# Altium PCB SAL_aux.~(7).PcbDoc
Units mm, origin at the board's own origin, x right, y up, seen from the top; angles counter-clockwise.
Board outline 56 x 58 mm, 2 copper layers (Top Layer, Bottom Layer); 28 components, 47 nets, 135 pads, 5 vias.
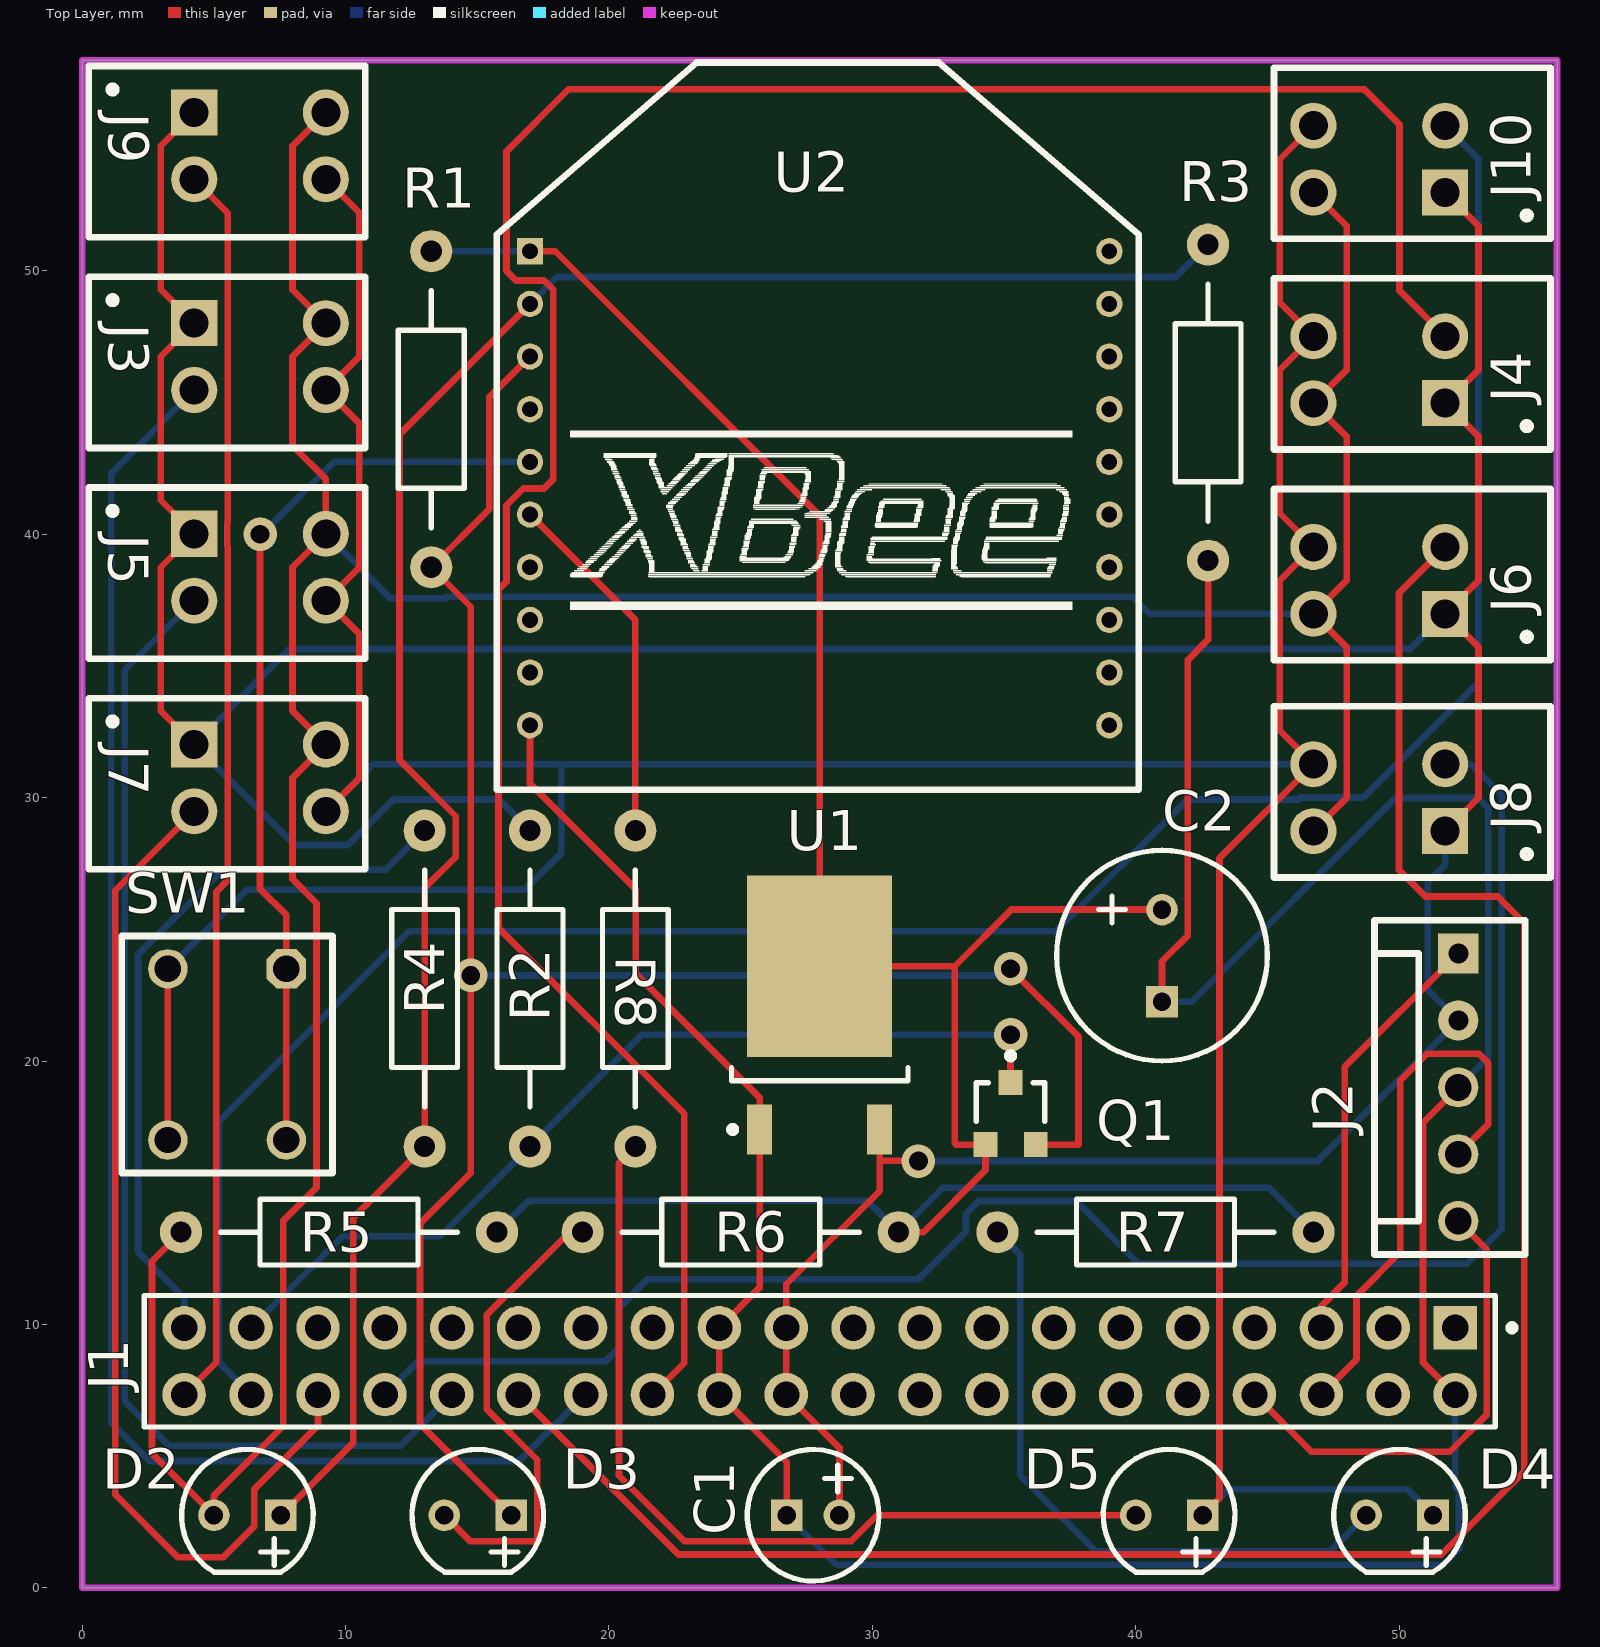
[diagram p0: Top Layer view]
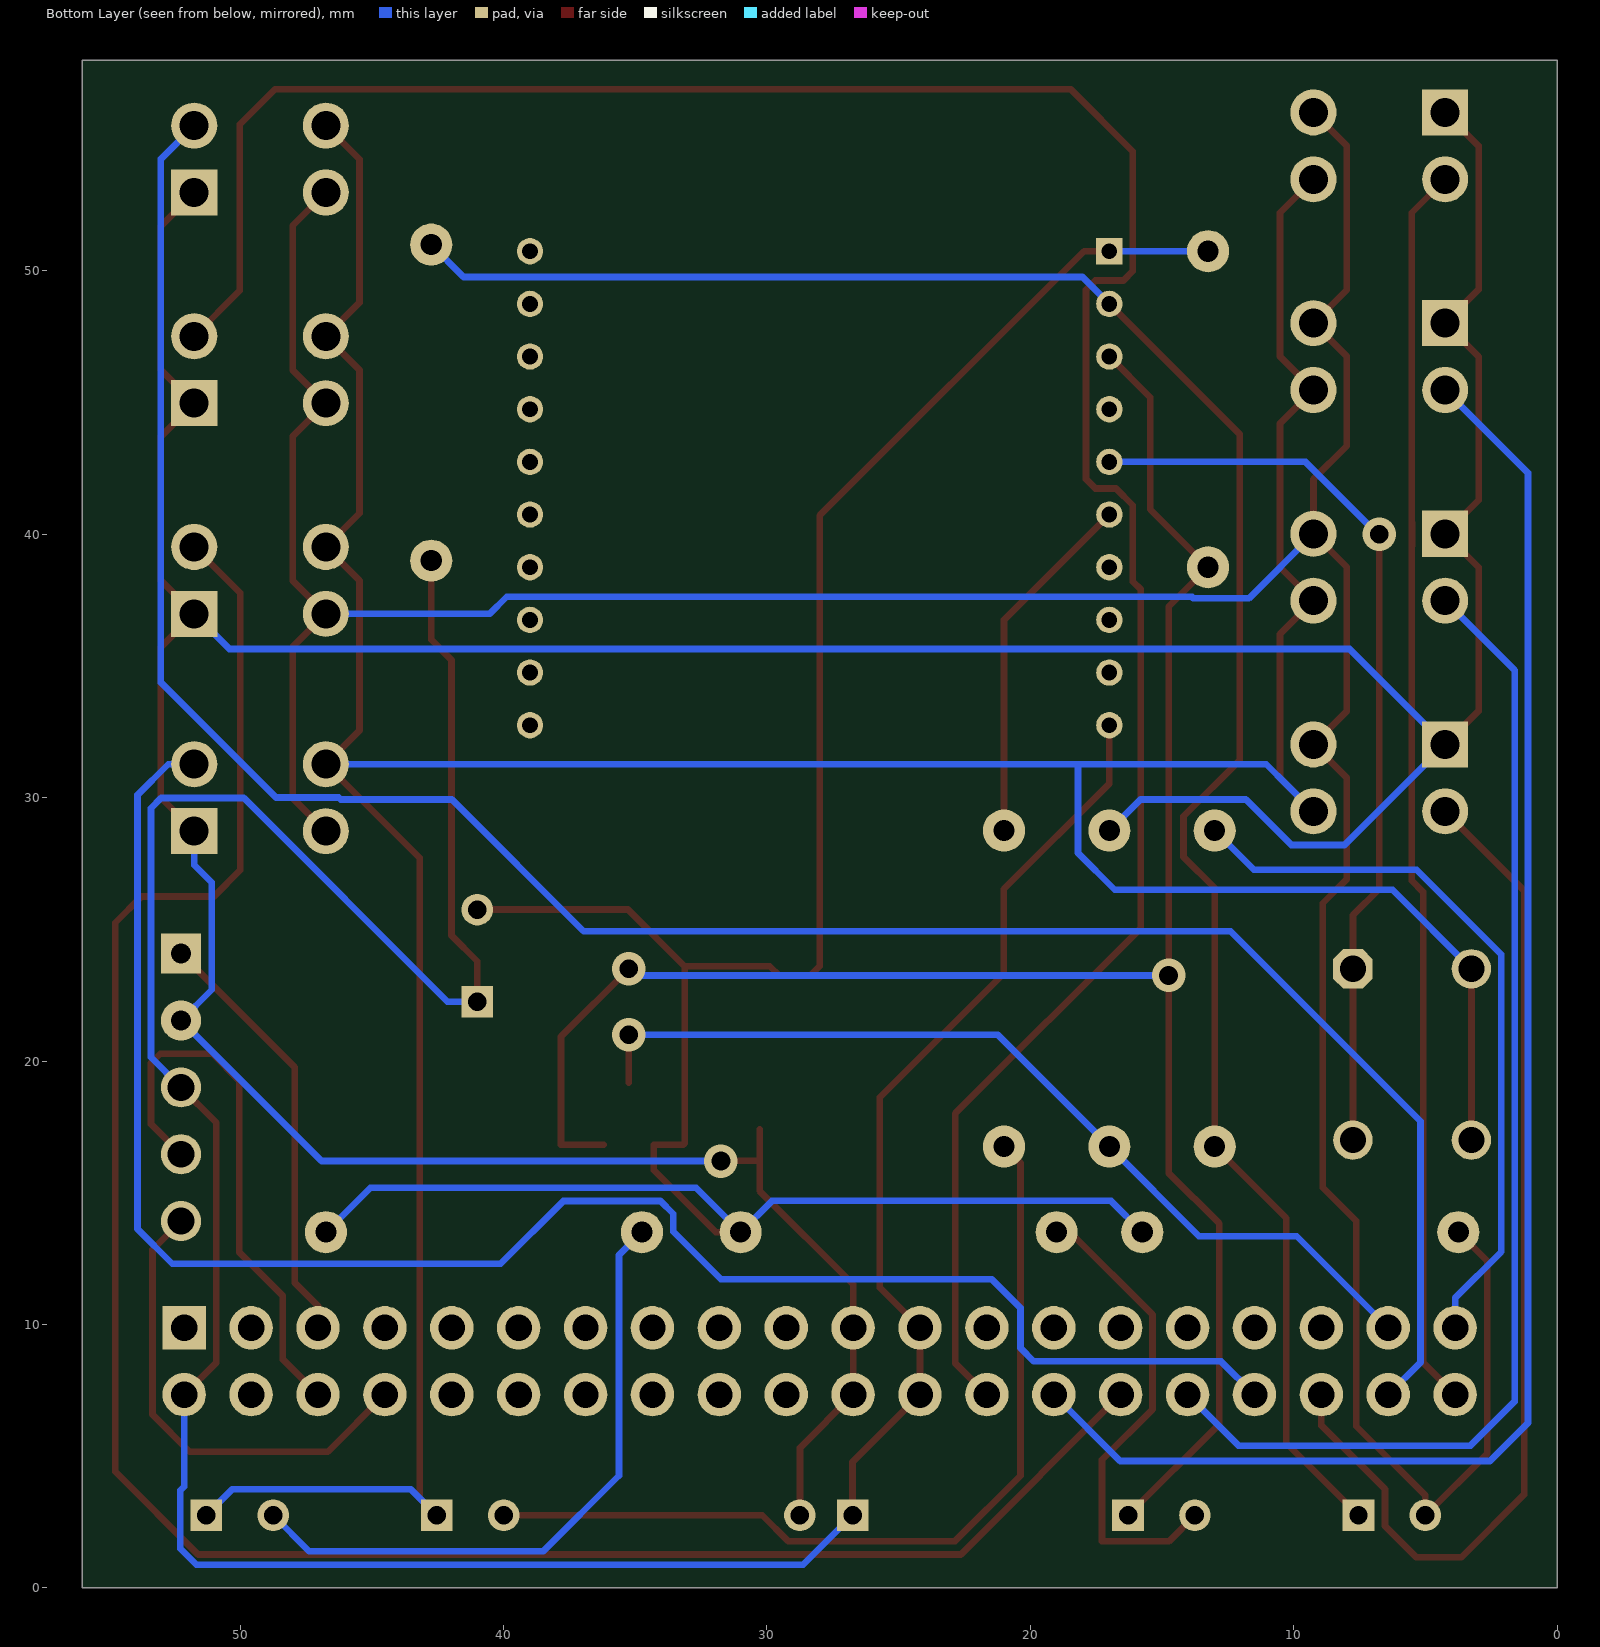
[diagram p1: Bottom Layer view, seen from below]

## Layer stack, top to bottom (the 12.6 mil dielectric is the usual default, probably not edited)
Top Layer: signal copper 0.0356
Dielectric: dielectric 0.32, FR-4, Dk 4.8
Bottom Layer: signal copper 0.0356

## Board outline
0,0 0,58 56,58 56,0

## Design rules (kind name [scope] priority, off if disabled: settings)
Clearance [All] p1: gap=0.254
PolygonConnect [All] p1: connectstyle=Relief reliefconductorwidth=0.254 reliefentries=4 polygonreliefangle="90 Angle"
RoomDefinition SAL_aux [InComponentClass('SAL_aux')] p1: confinementstyle=ConfineIn formatcopy=TRUE lockcomponents=FALSE outline 0,0 56,0 56,58 0,58
RoutingVias [All] p1: holewidth=0.711 width=1.27 viastyle="Through Hole" minholewidth=0.711 minwidth=1.27 maxholewidth=0.711 maxwidth=1.27
SilkscreenOverComponentPads [All] p1: minsilkscreentomaskgap=0.254
SolderMaskExpansion [All] p1: expansion=0.102
TestPointUsage [All] p1: valid=0 allowmultiple=FALSE
Testpoint [All] p1: side=15 testpointundercomponent=TRUE minsize=1.016 maxsize=2.54 preferedsize=1.524 minholesize=0 maxholesize=1.016 preferedholesize=0.813 testpointgrid=0.025 style=1023 order=0123456789
Width [All] p1: maxlimit=0.254 minlimit=0.254 preferedwidth=0.254
23 further rules are at their usual default settings.

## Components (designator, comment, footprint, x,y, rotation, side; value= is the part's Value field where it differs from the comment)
C1 "10 uF" "PANASONIC ECA1HAM100X" 26.75,2.75 r0 top
C2 "100 uF" "PANASONIC ECA1HAM101X" 41,22.25 r90 top
D2 "Yellow" "VISHAY TLLR4401" 5,2.75 r0 top
D3 "Red" "VISHAY TLLR4401" 13.75,2.75 r0 top
D4 "Green" "VISHAY TLLR4401" 48.75,2.75 r0 top
D5 "Blue" "VISHAY TLLR4401" 40,2.75 r0 top
J1 "SSW-120-01-G-D" "SAMTEC SSW-120-1-G-D" 28,8.6 r180 top locked
J2 "I2C Connector" "TYCO 640456-5" 52.25,19 r90 top
J3 "WAGO 234-502" "WAGO 234-502" 6.75,46.75 r270 top locked
J4 "WAGO 234-502" "WAGO 234-502" 49.25,46.25 r90 top locked
J5 "WAGO 234-502" "WAGO 234-502" 6.75,38.75 r270 top locked
J6 "WAGO 234-502" "WAGO 234-502" 49.25,38.25 r90 top locked
J7 "WAGO 234-502" "WAGO 234-502" 6.75,30.75 r270 top locked
J8 "WAGO 234-502" "WAGO 234-502" 49.25,30 r90 top locked
J9 "WAGO 234-502" "WAGO 234-502" 6.75,54.75 r270 top locked
J10 "WAGO 234-502" "WAGO 234-502" 49.25,54.25 r90 top locked
Q1 "BSS138" SOT23 35.25,18 r0 top
R1 "10K" Resistência 13.25,38.75 r90 top
R2 "10K" Resistência 17,16.75 r90 top
R3 "10K" Resistência 42.75,39 r90 top
R4 "10K" Resistência 13,16.75 r90 top
R5 "1K" Resistência 15.75,13.5 r180 top
R6 "1K" Resistência 31,13.5 r180 top
R7 "1K" Resistência 46.75,13.5 r180 top
R8 "1K" Resistência 21,28.75 r270 top
SW1 "OMRON B3F-1002" "OMRON B3F-1002" 5.5,20.25 r90 top
U1 "LM1117DT-3.3" TD03B_N 28,21.75 r90 top
U2 "XBee" XBee 28,40.75 r0 top locked

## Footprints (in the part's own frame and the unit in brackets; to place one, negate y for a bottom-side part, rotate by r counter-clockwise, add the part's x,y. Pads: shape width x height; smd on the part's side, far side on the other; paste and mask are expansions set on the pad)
"OMRON B3F-1002" [mm] "6.0mm Tactil Switch"
  oct 1.5x1.5 hole 1: 1(3.25,-2.25)
  round 1.5 hole 1: 2(-3.25,-2.25) 3(3.25,2.25) 4(-3.25,2.25)
  silkscreen extent -4.5,-4 4.5,4
"PANASONIC ECA1HAM100X" [mm]
  rect 1.2x1.2 hole 0.7: 1(0,0)
  round 1.2 hole 0.7: 2(2,0)
  silkscreen extent -1.5,-2.5 3.5,2.5
"PANASONIC ECA1HAM101X" [mm]
  rect 1.2x1.2 hole 0.7: 1(0,0)
  round 1.2 hole 0.7: 2(3.5,0)
  silkscreen extent -2.25,-4 5.75,4
Resistência [mm]
  round 1.6 hole 0.8: 1(0,0) 2(12,0)
  silkscreen extent 1.5,-1.25 10.5,1.25
"SAMTEC SSW-120-1-G-D" [mm]
  rect 1.65x1.65 / inner round 1.65 / far side rect 1.65x1.65 hole 1 mask+0: 1(-24.13,-1.27)
  round 1.65 hole 1 mask+0: 2(-24.13,1.27) 3(-21.59,-1.27) 4(-21.59,1.27) 5(-19.05,-1.27) 6(-19.05,1.27) 7(-16.51,-1.27) 8(-16.51,1.27) 9(-13.97,-1.27) 10(-13.97,1.27) 11(-11.43,-1.27) 12(-11.43,1.27) 13(-8.89,-1.27) 14(-8.89,1.27) 15(-6.35,-1.27) 16(-6.35,1.27) 17(-3.81,-1.27) 18(-3.81,1.27) 19(-1.27,-1.27) 20(-1.27,1.27) 21(1.27,-1.27) 22(1.27,1.27) 23(3.81,-1.27) 24(3.81,1.27) 25(6.35,-1.27) 26(6.35,1.27) 27(8.89,-1.27) 28(8.89,1.27) 29(11.43,-1.27) 30(11.43,1.27) 31(13.97,-1.27) 32(13.97,1.27) 33(16.51,-1.27) 34(16.51,1.27) 35(19.05,-1.27) 36(19.05,1.27) 37(21.59,-1.27) 38(21.59,1.27) 39(24.13,-1.27) 40(24.13,1.27)
  silkscreen extent -26.41,-2.5 25.65,2.5
SOT23 [mm] "SOT-23; 3 Leads; Body 3.1 x 2.5 mm, inc. leads (LxW max), Alternate Lead Configuration"
  rect 0.9x0.95 smd: 1(0,1.175) 2(0.95,-1.175) 3(-0.95,-1.175)
  silkscreen extent -1.3,-0.3 1.3,2.32
TD03B_N [mm] "D-PAK, 4-Leads, Body 6.1x6.6mm, Pitch 2.29mm, Lead Span 9.7mm, IPC Medium Density"
  rect 1.9x0.95 smd: 1(-4.35,2.28) 3(-4.35,-2.28)
  rect 6.9x5.5 smd: 4(1.85,0)
  silkscreen extent -4.47,-3.35 -2,3.43, body extent -2.5,-3.35 3.7,3.35, height 2.38
"TYCO 640456-5" [mil] "I2C Connector"
  rect 60x60 hole 30: 1(200,0)
  round 60 hole 30: 2(100,0)
  round 60 hole 40.16: 3(0,0) 4(-100,0) 5(-200,0)
  silkscreen extent -250,-100 250,125
"VISHAY TLLR4401" [mm] "3mm LED"
  round 1.2 hole 0.7: 1(0,0)
  rect 1.2x1.2 hole 0.7: 2(2.54,0)
  silkscreen extent -1.23,-2.17 3.77,2.5
"WAGO 234-502" [mm]
  rect 1.75x1.75 hole 1.1: 1(-1.27,-2.5)
  round 1.75 hole 1.1: 2(-1.27,2.5) 3(1.27,-2.5) 4(1.27,2.5)
  silkscreen extent -3.03,-6.5 3.47,4
XBee [mm] "ZigBee device"
  rect 1x1 hole 0.6: 1(-11,10)
  round 1 hole 0.6: 2(-11,8) 3(-11,6) 4(-11,4) 5(-11,2) 6(-11,0) 7(-11,-2) 8(-11,-4) 9(-11,-6) 10(-11,-8) 11(11,-8) 12(11,-6) 13(11,-4) 14(11,-2) 15(11,0) 16(11,2) 17(11,4) 18(11,6) 19(11,8) 20(11,10)
  silkscreen extent -12.26,-10.44 12.12,17.17

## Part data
C1: library part "PANASONIC ECA1HAM100X"
C2: library part "PANASONIC ECA1HAM101X"
D2 D3 D4 D5: library part "VISHAY TLLG4401", "Green LED PCB 3mm"
J1: library part "SAMTEC SSW-120-01-G-D"
J2: library part "TYCO 640456-5"
Q1: "N-Channel Enhancement Mode Vertical DMOS FET"
R1 R2 R3 R4 R5 R6 R7 R8: library part Resistência
SW1: "6.0mm Tact Switch"
U1: "800mA Low-Dropout Linear Regulator"

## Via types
v1: diameter 1.27, hole 0.711, Top Layer to Bottom Layer, 5 vias

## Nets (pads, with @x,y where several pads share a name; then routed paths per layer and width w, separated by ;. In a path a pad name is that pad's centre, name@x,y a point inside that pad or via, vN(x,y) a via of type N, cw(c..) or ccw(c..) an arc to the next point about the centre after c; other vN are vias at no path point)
1: D2.1 J3.2 J4.2 J5.2 J6.2 J7.2 J8.2 J9.2 J10.2 R5.2 | length 137.6
  Top Layer w0.254: R5.2 2.648,12.398 2.648,5.102 D2.1 5,3.504 7.626,6.13 7.626,13.928 8.896,15.198 8.896,25.993 7.982,26.907 7.982,30.752 J7.2 7.982,33.288 7.982,38.752 J5.2 9.25,42.097 7.982,43.365 7.982,46.752 J3.2 7.982,49.288 7.982,54.752 J9.2 ; J8.2 48.012,29.992 48.012,35.718 J6.2 48.012,38.242 48.012,43.718 J4.2 48.012,46.242 48.012,51.718 J10.2
  Bottom Layer w0.254: J5.2 11.701,37.569 13.801,37.569 13.863,37.631 39.881,37.631 40.532,36.98 J6.2 J6.2@46.75,37.25
3: D4.2 D5.2 J3.4 J4.4 J5.4 J6.4 J7.4 J8.4 J9.4 J10.4 SW1.3 SW1.4 | length 160.7
  Top Layer w0.254: SW1.4 SW1.3 ; J7.4 10.522,30.752 10.522,36.208 J5.4 10.522,38.752 10.522,44.208 J3.4 10.522,46.752 10.522,52.208 J9.4 ; D5.2 43.186,3.396 43.186,27.706 J8.4 45.472,32.548 45.472,38.242 J6.4 45.472,40.798 45.472,46.242 J4.4 45.472,48.798 45.472,54.242 J10.4
  Bottom Layer w0.254: SW1.3 6.251,26.501 16.795,26.501 18.192,27.898 18.192,31.27 ; D5.2 43.533,3.743 50.297,3.743 D4.2 ; J8.4 11.04,31.27 10.233,30.463 ; 10.233,30.463 J7.4 10.233,30.463
3.3V: C2.2 Q1.3 R1.2 R5.1 R6.1 R7.1 U1.4 U2.1 | length 96.7
  Top Layer w0.254: U2.1 17.959,50.75 28,40.709 U1.4 28.35,23.25 29.545,23.25 29.895,23.6 33.128,23.6 ; R6.1 31.938,13.5 34.3,15.862 Q1.3 33.175,16.825 33.128,16.872 33.128,23.6 ; C2.2 35.278,25.75 33.128,23.6
  Bottom Layer w0.254: R1.2 U2.1 ; R5.1 16.94,14.69 29.81,14.69 R6.1 32.689,15.189 45.061,15.189 R7.1
/INT: J1.20
/RESET: J1.5 J2.1 | length 16.4
  Top Layer w0.254: J1.5 47.05,10.698 47.936,11.584 47.936,19.766 J2.1
A0: J1.7
A4/LSDA: J1.1
A5/LSCL: J1.3
B5: J1.10
C0: J1.25
C1: J1.27
C2: J1.29
C5: J1.35
D0: J1.40 J9.3 | length 47.4
  Top Layer w0.254: J1.40 5.086,8.546 5.086,26.425 5.518,26.857 5.518,39.549 5.506,39.561 5.506,40.439 5.518,40.451 5.518,52.212 J9.3
D1: J1.38 J10.3 | length 87.3
  Bottom Layer w0.254: J1.38 5.188,8.552 5.188,17.713 12.401,24.926 36.963,24.926 41.967,29.93 46.183,29.93 46.259,30.006 48.647,30.006 53.016,34.375 53.016,54.254 J10.3
D2: J1.36 J7.3 | length 39.9
  Top Layer w0.254: J7.3 1.25,26.48 1.25,3.54 3.638,1.152 5.34,1.152 6.534,2.346 6.534,3.743 8.95,6.159 J1.36
D3: J1.34 J8.3 | length 67.4
  Bottom Layer w0.254: J1.34 12.754,8.594 19.869,8.594 20.377,9.102 20.377,10.626 21.469,11.718 31.756,11.718 33.559,13.522 33.559,14.198 34.042,14.681 37.734,14.681 40.113,12.302 52.584,12.302 53.901,13.619 53.901,30.107 52.738,31.27 J8.3
D4: J1.32 J5.3 | length 45.4
  Bottom Layer w0.254: J5.3 1.611,34.841 1.611,7.065 3.283,5.394 12.094,5.394 J1.32
D5: J1.30 J6.3 | length 81.4
  Top Layer w0.254: J1.30 22.639,1.261 51.601,1.261 54.75,4.41 54.75,25.25 53.75,26.25 51,26.25 50,27.25 50,37.77 J6.3
D6: J1.28 J3.3 | length 60.2
  Bottom Layer w0.254: J3.3 1.103,42.333 1.103,6.252 2.546,4.809 16.589,4.809 J1.28
D7: J1.26 J4.3 | length 97.5
  Top Layer w0.254: J1.26 22.856,8.536 22.856,18.002 15.805,25.053 15.805,37.906 16.11,38.21 16.11,41.106 16.745,41.741 17.532,41.741 17.888,42.097 17.888,49.285 17.532,49.64 16.465,49.64 16.11,49.996 16.11,54.543 18.472,56.905 48.672,56.905 50.019,55.559 50.019,49.251 J4.3
DIN: D3.2 Q1.2 R1.1 U2.3 | length 78.4
  Top Layer w0.254: D3.2 12.824,6.216 12.824,13.824 14.75,15.75 v1(14.75,23.25) 14.75,37.25 R1.1 15.449,40.949 15.449,45.199 U2.3 ; v1(35.25,23.5) 37.825,20.925 37.825,16.825 Q1.2
  Bottom Layer w0.254: v1(14.75,23.25) 35,23.25 v1(35.25,23.5)
DOUT: D2.2 R3.2 R4.1 U2.2 | length 78.4
  Top Layer w0.254: D2.2 10.284,5.494 10.284,14.034 R4.1 13,26.566 14.181,27.747 14.181,29.295 12.046,31.43 12.046,43.796 U2.2
  Bottom Layer w0.254: U2.2 18.017,49.767 41.517,49.767 R3.2
EYEB: J1.19
EYEF: J1.9
EYEL: J1.13
EYER: J1.11
NetD3_1: D3.1 R6.2 | length 17.8
  Top Layer w0.254: D3.1 14.739,1.761 17.278,1.761 17.278,4.86 15.364,6.774 15.364,10.369 R6.2@18.494,13.5
NetD4_1: D4.1 R7.2 | length 24.5
  Bottom Layer w0.254: R7.2 35.62,12.63 35.62,4.25 ; 35.63,4.25 38.5,1.38 47.38,1.38 D4.1
NetD5_1: D5.1 R8.2 | length 33.8
  Top Layer w0.254: R8.2 20.377,16.127 20.377,4.251 22.858,1.769 29.198,1.769 30.179,2.75 D5.1
PWM1/SERVOR: J1.18
PWM2/SERVOL: J1.16
PWM3: J1.14
PWM4: J1.12
RESET: SW1.1 SW1.2 U2.5 | length 35.3
  Top Layer w0.254: v1(6.75,40) 6.75,26.539 7.75,25.539 SW1.1 SW1.2
  Bottom Layer w0.254: v1(6.75,40) 6.508,40 6.799,40 9.549,42.75 U2.5
RSSI: R8.1 U2.6 | length 13.7
  Top Layer w0.254: U2.6 21,36.75 R8.1
RX: J1.39 R4.2 | length 27.7
  Bottom Layer w0.254: J1.39 3.87,11.001 2.119,12.752 2.119,24.042 5.34,27.263 11.513,27.263 R4.2
SCL: J1.31
SDA: J1.33
TX: J1.37 Q1.1 R2.1 | length 34.7
  Top Layer w0.254: Q1.1 35.25,20.394 v1@35.261,20.405
  Bottom Layer w0.254: J1.37 9.884,13.344 13.594,13.344 R2.1 21.25,21 v1(35.25,21)
US_B: J1.17
US_F: J1.15
V+: J1.4
VDD: C1.2 J1.21 J1.22 J2.2 J3.1 J4.1 J5.1 J6.1 J7.1 J8.1 J9.1 J10.1 R2.2 U1.3 | length 169.2
  Top Layer w0.254: J7.1 2.978,33.292 2.978,38.748 J5.1 2.978,41.292 2.978,46.748 J3.1 2.978,49.292 2.978,54.748 J9.1 ; C1.2 28.75,5.31 J1.22 J1.21 26.73,11.521 30.28,15.071 30.28,16.214 ; U1.3 30.28,16.214 ; v1@31.75,16.5 31.6,16.5 31.314,16.214 30.28,16.214 ; J8.1 53.016,29.996 53.016,35.714 J6.1 53.016,38.246 53.016,43.714 J4.1 53.016,46.246 53.016,51.714 J10.1
  Bottom Layer w0.254: R2.2 15.819,29.931 11.817,29.931 10.089,28.203 8.067,28.203 J7.1 7.875,35.645 50.415,35.645 J6.1 ; v1@31.75,16.5 v1(31.75,16.2) 46.91,16.2 J2.2 51.085,22.705 51.085,26.776 51.75,27.441 J8.1
VSS: C1.1 C2.1 J1.2 J1.23 J1.24 J2.3 R3.1 U1.1 U2.10 | length 124.8
  Top Layer w0.254: U2.10 17,30.538 21.012,26.526 21.012,23.326 25.72,18.618 U1.1 25.72,11.4 J1.23 J1.24 26.75,4.77 C1.1 ; C2.1 41,23.788 41.981,24.769 41.981,35.231 42.75,36 R3.1 ; J1.2 50.908,8.552 50.908,17.658 J2.3
  Bottom Layer w0.254: C1.1 28.628,0.872 51.67,0.872 52.279,1.482 52.279,3.692 52.13,3.841 J1.2 ; C2.1 42.13,22.25 49.866,29.986 53.006,29.986 53.393,29.599 53.393,20.143 J2.3
XAXIS: J1.8 J2.5 | length 18.1
  Top Layer w0.254: J1.8 46.675,5.165 51.924,5.165 53.336,6.577 53.336,12.834 J2.5
YAXIS: J1.6 J2.4 | length 21
  Top Layer w0.254: J1.6 48.384,8.664 48.384,11.083 50.044,12.743 50.044,19.262 51.06,20.278 53.041,20.278 53.393,19.926 53.393,17.603 J2.4
pads on no net: U2.4 U2.7 U2.8 U2.9 U2.11 U2.12 U2.13 U2.14 U2.15 U2.16 U2.17 U2.18 U2.19 U2.20

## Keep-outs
Top Layer:
  the board outline again, w0.254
